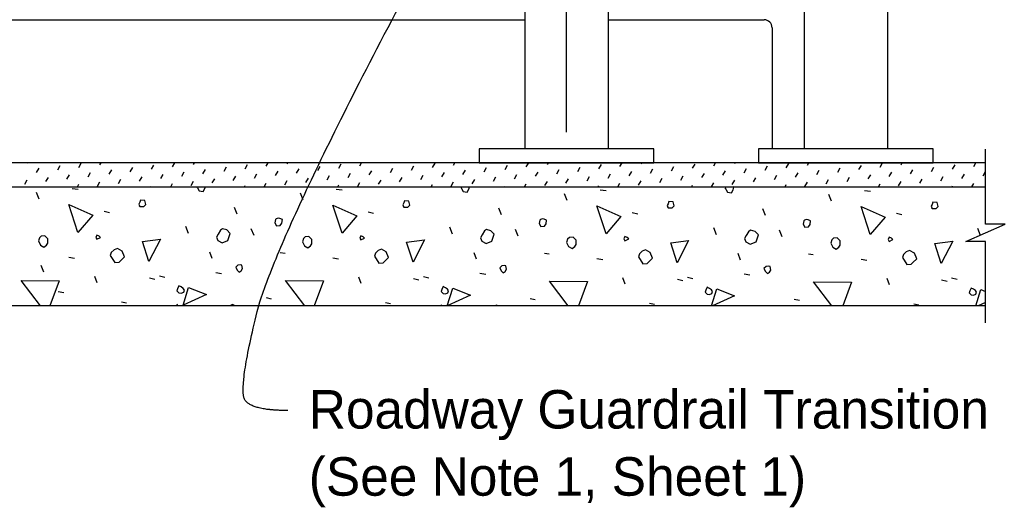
# Model space of a CAD drawing. Extents: x 21587 to 21656.3, y 56117.4 to 56157.3.
# Drawn here: x 21599.26 to 21604.43, y 56132.25 to 56134.8 of the extents above; entities that cross this region are included whole.
import ezdxf

# ---------------------------------------------------------------- set-up
doc = ezdxf.new("R2010")
doc.units = 0
for name, color, linetype in [('AdhocPoint_dp', 7, 'Continuous'), ('Patterning', 7, 'Continuous'), ('PlotBorder_dp', 7, 'Continuous'), ('TextMisc', 7, 'Continuous')]:
    doc.layers.add(name, color=color, linetype=linetype)

msp = doc.modelspace()

# ---------------------------------------------------------------- linework, layer by layer
at = {"layer": 'AdhocPoint_dp'}
for p, q in [((21593.9596, 56134.8009), (21601.9067, 56134.8009)), ((21602.3442, 56134.8009), (21603.1616, 56134.8009)), ((21603.2033, 56134.7592), (21603.2033, 56134.124)), ((21604.323, 56134.0511), (21593.9596, 56134.0511)), ((21593.9596, 56133.926), (21604.323, 56133.926)), ((21604.323, 56133.301), (21599.1795, 56133.301))]:
    msp.add_line(p, q, dxfattribs=at)
msp.add_arc((21603.1616, 56134.7592), 0.0417, 0, 90, dxfattribs=at)
at = {"layer": 'Patterning'}
for p, q in [((21602.3442, 56136.8633), (21602.3442, 56134.124)), ((21603.8089, 56136.8633), (21603.8089, 56134.124)), ((21601.9067, 56135.0302), (21601.9067, 56134.124)), ((21603.3714, 56135.0302), (21603.3714, 56134.124))]:
    msp.add_line(p, q, dxfattribs=at)
for points in [[(21602.5838, 56134.0511), (21602.5838, 56134.124), (21601.6671, 56134.124), (21601.6671, 56134.0511)], [(21604.0485, 56134.0511), (21604.0485, 56134.124), (21603.1318, 56134.124), (21603.1318, 56134.0511)]]:
    msp.add_lwpolyline(points, close=True, dxfattribs=at)
at = {"layer": 'PlotBorder_dp'}
msp.add_lwpolyline([(21604.323, 56133.2118), (21604.323, 56133.6391), (21604.2196, 56133.6391), (21604.323, 56133.6841), (21604.4263, 56133.7291), (21604.323, 56133.7291), (21604.323, 56134.1231)], dxfattribs=at)
msp.add_open_spline([(21600.6643, 56132.7531), (21600.4788, 56132.7531), (21600.4035, 56132.8585), (21600.5941, 56133.6459), (21601.3715, 56135.1053)], degree=2, dxfattribs=at)
at = {"layer": 'TextMisc'}
for p, q in [((21602.1255, 56134.2122), (21602.1255, 56137.1851)), ((21599.2983, 56134.05), (21599.299, 56134.0511)), ((21599.5684, 56134.0271), (21599.5814, 56134.0495)), ((21599.6791, 56134.04), (21599.6855, 56134.0511)), ((21600.0598, 56134.0301), (21600.072, 56134.0511)), ((21600.1704, 56134.0431), (21600.1751, 56134.0511)), ((21600.5512, 56134.0331), (21600.5616, 56134.0511)), ((21600.6618, 56134.0461), (21600.6647, 56134.0511)), ((21600.9319, 56134.0232), (21600.9449, 56134.0456)), ((21601.0425, 56134.0361), (21601.0512, 56134.0511)), ((21601.1532, 56134.0491), (21601.1543, 56134.0511)), ((21601.4233, 56134.0262), (21601.4362, 56134.0486)), ((21601.5339, 56134.0392), (21601.5408, 56134.0511)), ((21601.9146, 56134.0292), (21601.9273, 56134.0511)), ((21602.0253, 56134.0422), (21602.0304, 56134.0511)), ((21602.406, 56134.0322), (21602.4169, 56134.0511)), ((21602.5166, 56134.0452), (21602.52, 56134.0511)), ((21602.7867, 56134.0223), (21602.7997, 56134.0447)), ((21602.8974, 56134.0353), (21602.9065, 56134.0511)), ((21603.008, 56134.0482), (21603.0097, 56134.0511)), ((21603.2781, 56134.0253), (21603.2911, 56134.0477)), ((21603.3887, 56134.0383), (21603.3961, 56134.0511)), ((21603.7695, 56134.0283), (21603.7824, 56134.0507)), ((21603.8801, 56134.0413), (21603.8858, 56134.0511)), ((21604.2608, 56134.0314), (21604.2723, 56134.0511)), ((21599.3472, 56134.0012), (21599.3601, 56134.0235)), ((21599.4578, 56134.0141), (21599.4708, 56134.0365)), ((21599.6173, 56133.9782), (21599.6302, 56134.0006)), ((21599.7279, 56133.9912), (21599.7409, 56134.0136)), ((21599.8385, 56134.0042), (21599.8515, 56134.0266)), ((21599.9492, 56134.0171), (21599.9621, 56134.0395)), ((21600.1086, 56133.9813), (21600.1216, 56134.0037)), ((21600.2193, 56133.9942), (21600.2322, 56134.0166)), ((21600.3299, 56134.0072), (21600.3429, 56134.0296)), ((21600.4405, 56134.0202), (21600.4535, 56134.0426)), ((21600.4894, 56133.9713), (21600.5023, 56133.9937)), ((21600.6, 56133.9843), (21600.613, 56134.0067)), ((21600.7106, 56133.9973), (21600.7236, 56134.0196)), ((21600.8213, 56134.0102), (21600.8342, 56134.0326)), ((21600.9807, 56133.9743), (21600.9937, 56133.9967)), ((21601.0914, 56133.9873), (21601.1043, 56134.0097)), ((21601.202, 56134.0003), (21601.215, 56134.0227)), ((21601.3126, 56134.0132), (21601.3256, 56134.0356)), ((21601.4721, 56133.9774), (21601.4851, 56133.9998)), ((21601.5827, 56133.9903), (21601.5957, 56134.0127)), ((21601.6934, 56134.0033), (21601.7063, 56134.0257)), ((21601.804, 56134.0163), (21601.817, 56134.0386)), ((21601.9635, 56133.9804), (21601.9764, 56134.0028)), ((21602.0741, 56133.9933), (21602.0871, 56134.0157)), ((21602.1847, 56134.0063), (21602.1977, 56134.0287)), ((21602.2954, 56134.0193), (21602.3083, 56134.0417)), ((21602.3442, 56133.9704), (21602.3572, 56133.9928)), ((21602.4548, 56133.9834), (21602.4678, 56134.0058)), ((21602.5655, 56133.9964), (21602.5784, 56134.0188)), ((21602.6761, 56134.0093), (21602.6891, 56134.0317)), ((21602.8356, 56133.9735), (21602.8485, 56133.9959)), ((21602.9462, 56133.9864), (21602.9592, 56134.0088)), ((21603.0568, 56133.9994), (21603.0698, 56134.0218)), ((21603.1675, 56134.0124), (21603.1804, 56134.0347)), ((21603.3269, 56133.9765), (21603.3399, 56133.9989)), ((21603.4376, 56133.9894), (21603.4505, 56134.0118)), ((21603.5482, 56134.0024), (21603.5612, 56134.0248)), ((21603.6588, 56134.0154), (21603.6718, 56134.0378)), ((21603.8183, 56133.9795), (21603.8313, 56134.0019)), ((21603.9289, 56133.9925), (21603.9419, 56134.0149)), ((21604.0396, 56134.0054), (21604.0525, 56134.0278)), ((21604.1502, 56134.0184), (21604.1632, 56134.0408)), ((21604.199, 56133.9696), (21604.212, 56133.9919)), ((21604.3097, 56133.9825), (21604.3226, 56134.0049)), ((21599.2854, 56133.9394), (21599.2983, 56133.9617)), ((21599.396, 56133.9523), (21599.409, 56133.9747)), ((21599.5066, 56133.9653), (21599.5196, 56133.9877)), ((21599.6661, 56133.9294), (21599.6791, 56133.9518)), ((21599.7767, 56133.9424), (21599.7897, 56133.9648)), ((21599.8874, 56133.9553), (21599.9003, 56133.9777)), ((21599.998, 56133.9683), (21600.011, 56133.9907)), ((21600.0506, 56133.926), (21600.0598, 56133.9419)), ((21600.1575, 56133.9324), (21600.1704, 56133.9548)), ((21600.2681, 56133.9454), (21600.2811, 56133.9678)), ((21600.3787, 56133.9584), (21600.3917, 56133.9808)), ((21600.5403, 56133.926), (21600.5512, 56133.9449)), ((21600.6488, 56133.9355), (21600.6618, 56133.9578)), ((21600.7595, 56133.9484), (21600.7724, 56133.9708)), ((21600.8701, 56133.9614), (21600.8831, 56133.9838)), ((21601.0299, 56133.926), (21601.0425, 56133.9479)), ((21601.1402, 56133.9385), (21601.1532, 56133.9609)), ((21601.2508, 56133.9514), (21601.2638, 56133.9738)), ((21601.3615, 56133.9644), (21601.3744, 56133.9868)), ((21601.5209, 56133.9285), (21601.5339, 56133.9509)), ((21601.6316, 56133.9415), (21601.6445, 56133.9639)), ((21601.7422, 56133.9545), (21601.7552, 56133.9768)), ((21601.8528, 56133.9674), (21601.8658, 56133.9898)), ((21601.906, 56133.926), (21601.9146, 56133.941)), ((21602.0123, 56133.9315), (21602.0253, 56133.9539)), ((21602.1229, 56133.9445), (21602.1359, 56133.9669)), ((21602.2336, 56133.9575), (21602.2465, 56133.9799)), ((21602.3956, 56133.926), (21602.406, 56133.944)), ((21602.5037, 56133.9346), (21602.5166, 56133.957)), ((21602.6143, 56133.9475), (21602.6273, 56133.9699)), ((21602.7249, 56133.9605), (21602.7379, 56133.9829)), ((21602.8852, 56133.926), (21602.8974, 56133.947)), ((21602.995, 56133.9376), (21603.008, 56133.96)), ((21603.1057, 56133.9506), (21603.1186, 56133.9729)), ((21603.2163, 56133.9635), (21603.2293, 56133.9859)), ((21603.3758, 56133.9276), (21603.3887, 56133.95)), ((21603.4864, 56133.9406), (21603.4994, 56133.963)), ((21603.597, 56133.9536), (21603.61, 56133.976)), ((21603.7077, 56133.9665), (21603.7206, 56133.9889)), ((21603.8671, 56133.9307), (21603.8801, 56133.9531)), ((21603.9778, 56133.9436), (21603.9907, 56133.966)), ((21604.0884, 56133.9566), (21604.1014, 56133.979)), ((21604.2509, 56133.926), (21604.2608, 56133.9431)), ((21599.3606, 56133.8606), (21599.3465, 56133.8959)), ((21599.5332, 56133.9165), (21599.565, 56133.913)), ((21599.561, 56133.926), (21599.5684, 56133.9388)), ((21599.9475, 56133.926), (21599.9492, 56133.9289)), ((21600.4371, 56133.926), (21600.4405, 56133.9319)), ((21600.7453, 56133.857), (21600.7311, 56133.8924)), ((21600.9179, 56133.913), (21600.9497, 56133.9094)), ((21600.9267, 56133.926), (21600.9319, 56133.9349)), ((21601.4164, 56133.926), (21601.4233, 56133.938)), ((21601.8028, 56133.926), (21601.804, 56133.928)), ((21602.13, 56133.8535), (21602.1158, 56133.8889)), ((21602.2925, 56133.926), (21602.2954, 56133.931)), ((21602.3026, 56133.9094), (21602.3344, 56133.9059)), ((21602.7821, 56133.926), (21602.7867, 56133.9341)), ((21603.2717, 56133.926), (21603.2781, 56133.9371)), ((21603.6582, 56133.926), (21603.6588, 56133.9271)), ((21603.6873, 56133.9059), (21603.7191, 56133.9024)), ((21603.7613, 56133.926), (21603.7695, 56133.9401)), ((21604.1478, 56133.926), (21604.1502, 56133.9302)), ((21603.5146, 56133.85), (21603.5005, 56133.8853)), ((21599.7012, 56133.7981), (21599.7294, 56133.791)), ((21600.3994, 56133.7822), (21600.3853, 56133.8175)), ((21601.0858, 56133.7945), (21601.1141, 56133.7875)), ((21601.7841, 56133.7786), (21601.77, 56133.814)), ((21602.4705, 56133.791), (21602.4988, 56133.7839)), ((21603.1688, 56133.7751), (21603.1546, 56133.8104)), ((21603.8552, 56133.7875), (21603.8835, 56133.7804)), ((21600.1431, 56133.6814), (21600.129, 56133.7168)), ((21600.4872, 56133.6697), (21600.473, 56133.705)), ((21601.5278, 56133.6779), (21601.5136, 56133.7132)), ((21601.8719, 56133.6661), (21601.8577, 56133.7015)), ((21602.9125, 56133.6743), (21602.8983, 56133.7097)), ((21603.2565, 56133.6626), (21603.2424, 56133.6979)), ((21604.2971, 56133.6708), (21604.283, 56133.7062)), ((21600.2686, 56133.5488), (21600.2562, 56133.5824)), ((21600.6251, 56133.5813), (21600.6498, 56133.5777)), ((21601.6533, 56133.5453), (21601.6409, 56133.5789)), ((21599.5162, 56133.5565), (21599.5462, 56133.5512)), ((21600.9008, 56133.553), (21600.9309, 56133.5477)), ((21602.0098, 56133.5777), (21602.0345, 56133.5742)), ((21602.2855, 56133.5494), (21602.3156, 56133.5441)), ((21603.038, 56133.5417), (21603.0256, 56133.5753)), ((21603.3944, 56133.5742), (21603.4192, 56133.5707)), ((21603.6702, 56133.5459), (21603.7003, 56133.5406)), ((21599.3845, 56133.4774), (21599.3704, 56133.5127)), ((21600.2874, 56133.477), (21600.3175, 56133.4717)), ((21599.6647, 56133.4222), (21599.6523, 56133.4558)), ((21599.9387, 56133.4487), (21599.967, 56133.4416)), ((21599.9911, 56133.4587), (21600.0194, 56133.4516)), ((21601.0493, 56133.4186), (21601.037, 56133.4522)), ((21601.3233, 56133.4451), (21601.3516, 56133.4381)), ((21601.3758, 56133.4551), (21601.404, 56133.4481)), ((21601.6721, 56133.4734), (21601.7022, 56133.4681)), ((21602.434, 56133.4151), (21602.4216, 56133.4487)), ((21602.708, 56133.4416), (21602.7363, 56133.4345)), ((21602.7604, 56133.4516), (21602.7887, 56133.4445)), ((21603.0568, 56133.4699), (21603.0868, 56133.4646)), ((21603.8187, 56133.4116), (21603.8063, 56133.4451)), ((21604.0927, 56133.4381), (21604.121, 56133.431)), ((21604.1451, 56133.4481), (21604.1734, 56133.441)), ((21599.4598, 56133.3773), (21599.4898, 56133.372)), ((21599.7919, 56133.3232), (21599.8185, 56133.3179)), ((21600.5508, 56133.3444), (21600.5773, 56133.3391)), ((21601.9355, 56133.3408), (21601.962, 56133.3355)), ((21603.3202, 56133.3373), (21603.3467, 56133.332)), ((21600.088, 56133.301), (21600.0848, 56133.3097)), ((21601.1766, 56133.3196), (21601.2031, 56133.3143)), ((21601.4713, 56133.301), (21601.4694, 56133.3061)), ((21602.5613, 56133.3161), (21602.5878, 56133.3108)), ((21602.8547, 56133.301), (21602.8541, 56133.3026)), ((21603.946, 56133.3126), (21603.9725, 56133.3073))]:
    msp.add_line(p, q, dxfattribs=at)
for points in [[(21600.1878, 56133.926), (21600.1908, 56133.9201)], [(21600.1908, 56133.9201), (21600.1997, 56133.9041), (21600.2209, 56133.9006), (21600.2297, 56133.9165), (21600.2321, 56133.926)], [(21601.5728, 56133.926), (21601.572, 56133.9236), (21601.5755, 56133.9165)], [(21601.5755, 56133.9165), (21601.5843, 56133.9006), (21601.6056, 56133.8971), (21601.6144, 56133.913), (21601.6177, 56133.926)], [(21602.9586, 56133.926), (21602.9566, 56133.9201), (21602.9602, 56133.913)], [(21602.9602, 56133.913), (21602.969, 56133.8971), (21602.9902, 56133.8935), (21602.9991, 56133.9094), (21603.0026, 56133.9236), (21603.0002, 56133.926)], [(21599.8885, 56133.8228), (21599.9098, 56133.8228), (21599.9204, 56133.8334), (21599.9151, 56133.8529), (21599.8921, 56133.8546), (21599.8885, 56133.844), (21599.8832, 56133.8352), (21599.8885, 56133.8228), (21599.885, 56133.8264)], [(21601.2732, 56133.8193), (21601.2944, 56133.8193), (21601.305, 56133.8299), (21601.2997, 56133.8493), (21601.2768, 56133.8511), (21601.2732, 56133.8405), (21601.2679, 56133.8317), (21601.2732, 56133.8193), (21601.2697, 56133.8228)], [(21602.6579, 56133.8158), (21602.6791, 56133.8158), (21602.6897, 56133.8264), (21602.6844, 56133.8458), (21602.6614, 56133.8476), (21602.6579, 56133.837), (21602.6526, 56133.8281), (21602.6579, 56133.8158), (21602.6544, 56133.8193)], [(21604.0426, 56133.8122), (21604.0638, 56133.8122), (21604.0744, 56133.8228), (21604.0691, 56133.8423), (21604.0461, 56133.844), (21604.0426, 56133.8334), (21604.0373, 56133.8246), (21604.0426, 56133.8122), (21604.039, 56133.8158)], [(21599.5639, 56133.6856), (21599.5162, 56133.8323), (21599.6417, 56133.7775), (21599.5639, 56133.6856)], [(21600.9486, 56133.682), (21600.9008, 56133.8288), (21601.0264, 56133.774), (21600.9486, 56133.682)], [(21602.3333, 56133.6785), (21602.2855, 56133.8252), (21602.411, 56133.7704), (21602.3333, 56133.6785)], [(21603.7179, 56133.675), (21603.6702, 56133.8217), (21603.7957, 56133.7669), (21603.7179, 56133.675)], [(21600.5968, 56133.7368), (21600.6056, 56133.7209), (21600.6251, 56133.7227), (21600.6339, 56133.7351), (21600.6357, 56133.7545), (21600.6233, 56133.7598), (21600.6145, 56133.7616), (21600.6039, 56133.758), (21600.6003, 56133.7545), (21600.5968, 56133.7368)], [(21601.9815, 56133.7333), (21601.9903, 56133.7174), (21602.0098, 56133.7192), (21602.0186, 56133.7315), (21602.0204, 56133.751), (21602.008, 56133.7563), (21601.9991, 56133.758), (21601.9885, 56133.7545), (21601.985, 56133.751), (21601.9815, 56133.7333)], [(21603.3661, 56133.7298), (21603.375, 56133.7138), (21603.3944, 56133.7156), (21603.4033, 56133.728), (21603.405, 56133.7474), (21603.3927, 56133.7527), (21603.3838, 56133.7545), (21603.3732, 56133.751), (21603.3697, 56133.7474), (21603.3661, 56133.7298)], [(21600.2969, 56133.6443), (21600.3199, 56133.6319), (21600.3499, 56133.6443), (21600.3623, 56133.6814), (21600.3446, 56133.6991), (21600.3216, 56133.7044), (21600.311, 56133.6973), (21600.2987, 56133.6779), (21600.2898, 56133.662), (21600.2969, 56133.6443)], [(21601.6816, 56133.6407), (21601.7046, 56133.6284), (21601.7346, 56133.6407), (21601.747, 56133.6779), (21601.7293, 56133.6955), (21601.7063, 56133.7008), (21601.6957, 56133.6938), (21601.6833, 56133.6743), (21601.6745, 56133.6584), (21601.6816, 56133.6407)], [(21603.0663, 56133.6372), (21603.0892, 56133.6248), (21603.1193, 56133.6372), (21603.1317, 56133.6743), (21603.114, 56133.692), (21603.091, 56133.6973), (21603.0804, 56133.6902), (21603.068, 56133.6708), (21603.0592, 56133.6549), (21603.0663, 56133.6372)], [(21599.3571, 56133.6414), (21599.3677, 56133.6202), (21599.3854, 56133.6096), (21599.3995, 56133.6202), (21599.4066, 56133.6308), (21599.4066, 56133.652), (21599.3907, 56133.6679), (21599.3712, 56133.6661), (21599.3624, 56133.6573), (21599.3571, 56133.6414)], [(21599.6629, 56133.6502), (21599.6823, 56133.659), (21599.6753, 56133.6661), (21599.6629, 56133.6714), (21599.6576, 56133.659), (21599.6629, 56133.6502)], [(21599.9363, 56133.5347), (21599.9027, 56133.639), (21599.9964, 56133.6514), (21599.9363, 56133.5347)], [(21600.7417, 56133.6378), (21600.7524, 56133.6166), (21600.77, 56133.606), (21600.7842, 56133.6166), (21600.7912, 56133.6272), (21600.7912, 56133.6484), (21600.7753, 56133.6644), (21600.7559, 56133.6626), (21600.7471, 56133.6537), (21600.7417, 56133.6378)], [(21601.0476, 56133.6467), (21601.067, 56133.6555), (21601.0599, 56133.6626), (21601.0476, 56133.6679), (21601.0423, 56133.6555), (21601.0476, 56133.6467)], [(21601.3209, 56133.5311), (21601.2874, 56133.6354), (21601.3811, 56133.6478), (21601.3209, 56133.5311)], [(21602.1264, 56133.6343), (21602.137, 56133.6131), (21602.1547, 56133.6025), (21602.1689, 56133.6131), (21602.1759, 56133.6237), (21602.1759, 56133.6449), (21602.16, 56133.6608), (21602.1406, 56133.659), (21602.1317, 56133.6502), (21602.1264, 56133.6343)], [(21602.4322, 56133.6431), (21602.4517, 56133.652), (21602.4446, 56133.659), (21602.4322, 56133.6644), (21602.4269, 56133.652), (21602.4322, 56133.6431)], [(21602.7056, 56133.5276), (21602.672, 56133.6319), (21602.7657, 56133.6443), (21602.7056, 56133.5276)], [(21603.5111, 56133.6308), (21603.5217, 56133.6096), (21603.5394, 56133.5989), (21603.5535, 56133.6096), (21603.5606, 56133.6202), (21603.5606, 56133.6414), (21603.5447, 56133.6573), (21603.5252, 56133.6555), (21603.5164, 56133.6467), (21603.5111, 56133.6308)], [(21603.8169, 56133.6396), (21603.8364, 56133.6484), (21603.8293, 56133.6555), (21603.8169, 56133.6608), (21603.8116, 56133.6484), (21603.8169, 56133.6396)], [(21604.0903, 56133.5241), (21604.0567, 56133.6284), (21604.1504, 56133.6407), (21604.0903, 56133.5241)], [(21599.7336, 56133.5654), (21599.7566, 56133.5282), (21599.7796, 56133.53), (21599.7884, 56133.5388), (21599.8079, 56133.5583), (21599.7955, 56133.5883), (21599.7707, 56133.6025), (21599.7531, 56133.5954), (21599.7389, 56133.5813), (21599.7336, 56133.5654)], [(21601.1183, 56133.5618), (21601.1413, 56133.5247), (21601.1642, 56133.5265), (21601.1731, 56133.5353), (21601.1925, 56133.5547), (21601.1802, 56133.5848), (21601.1554, 56133.5989), (21601.1377, 56133.5919), (21601.1236, 56133.5777), (21601.1183, 56133.5618)], [(21602.503, 56133.5583), (21602.5259, 56133.5212), (21602.5489, 56133.5229), (21602.5578, 56133.5318), (21602.5772, 56133.5512), (21602.5648, 56133.5813), (21602.5401, 56133.5954), (21602.5224, 56133.5883), (21602.5083, 56133.5742), (21602.503, 56133.5583)], [(21603.8876, 56133.5547), (21603.9106, 56133.5176), (21603.9336, 56133.5194), (21603.9424, 56133.5282), (21603.9619, 56133.5477), (21603.9495, 56133.5777), (21603.9248, 56133.5919), (21603.9071, 56133.5848), (21603.8929, 56133.5707), (21603.8876, 56133.5547)], [(21600.3988, 56133.4893), (21600.4094, 56133.4787), (21600.42, 56133.4858), (21600.4271, 56133.4964), (21600.4236, 56133.5141), (21600.4147, 56133.5159), (21600.4023, 56133.5141), (21600.3917, 56133.5035), (21600.3988, 56133.4893)], [(21601.7835, 56133.4858), (21601.7941, 56133.4752), (21601.8047, 56133.4823), (21601.8118, 56133.4929), (21601.8082, 56133.5106), (21601.7994, 56133.5123), (21601.787, 56133.5106), (21601.7764, 56133.4999), (21601.7835, 56133.4858)], [(21603.1682, 56133.4823), (21603.1788, 56133.4717), (21603.1894, 56133.4787), (21603.1964, 56133.4893), (21603.1929, 56133.507), (21603.1841, 56133.5088), (21603.1717, 56133.507), (21603.1611, 56133.4964), (21603.1682, 56133.4823)], [(21599.3679, 56133.301), (21599.2664, 56133.4345), (21599.4662, 56133.4328), (21599.4169, 56133.301)], [(21600.7531, 56133.301), (21600.6516, 56133.4345), (21600.8513, 56133.4328), (21600.8021, 56133.301)], [(21602.1351, 56133.301), (21602.0363, 56133.431), (21602.236, 56133.4292), (21602.1881, 56133.301)], [(21603.5171, 56133.301), (21603.4209, 56133.4275), (21603.6207, 56133.4257), (21603.5741, 56133.301)], [(21600.0936, 56133.3703), (21600.106, 56133.3685), (21600.1184, 56133.3738), (21600.1219, 56133.3844), (21600.1166, 56133.3933), (21600.106, 56133.4003), (21600.0936, 56133.4056), (21600.0865, 56133.3915), (21600.083, 56133.3809), (21600.0936, 56133.3703)], [(21600.116, 56133.3055), (21600.1442, 56133.3974), (21600.2379, 56133.3603), (21600.116, 56133.3055)], [(21601.4783, 56133.3667), (21601.4907, 56133.365), (21601.503, 56133.3703), (21601.5066, 56133.3809), (21601.5013, 56133.3897), (21601.4907, 56133.3968), (21601.4783, 56133.4021), (21601.4712, 56133.388), (21601.4677, 56133.3773), (21601.4783, 56133.3667)], [(21601.5006, 56133.302), (21601.5289, 56133.3939), (21601.6226, 56133.3568), (21601.5006, 56133.302)], [(21602.863, 56133.3632), (21602.8753, 56133.3614), (21602.8877, 56133.3667), (21602.8912, 56133.3773), (21602.8859, 56133.3862), (21602.8753, 56133.3933), (21602.863, 56133.3986), (21602.8559, 56133.3844), (21602.8524, 56133.3738), (21602.863, 56133.3632)], [(21602.8861, 56133.301), (21602.9136, 56133.3903), (21603.0073, 56133.3532), (21602.891, 56133.301)], [(21604.2476, 56133.3597), (21604.26, 56133.3579), (21604.2724, 56133.3632), (21604.2759, 56133.3738), (21604.2706, 56133.3827), (21604.26, 56133.3897), (21604.2476, 56133.395), (21604.2406, 56133.3809), (21604.237, 56133.3703), (21604.2476, 56133.3597)], [(21604.2719, 56133.301), (21604.2983, 56133.3868), (21604.323, 56133.377)], [(21600.3884, 56133.301), (21600.3882, 56133.302), (21600.3741, 56133.309), (21600.3606, 56133.301)], [(21601.7677, 56133.301), (21601.7587, 56133.3055), (21601.7512, 56133.301)], [(21603.1453, 56133.301), (21603.1434, 56133.302), (21603.1418, 56133.301)], [(21604.323, 56133.3187), (21604.2836, 56133.301)]]:
    msp.add_lwpolyline(points, dxfattribs=at)

# ---------------------------------------------------------------- texts
at = {"layer": 'PlotBorder_dp'}
for s, p in [('Roadway Guardrail Transition ', (21600.7744, 56132.6586)), ('(See Note 1, Sheet 1)', (21600.7744, 56132.3066))]:
    msp.add_text(s, height=0.2016, dxfattribs=at).set_placement(p)

doc.saveas('drawing.dxf')
